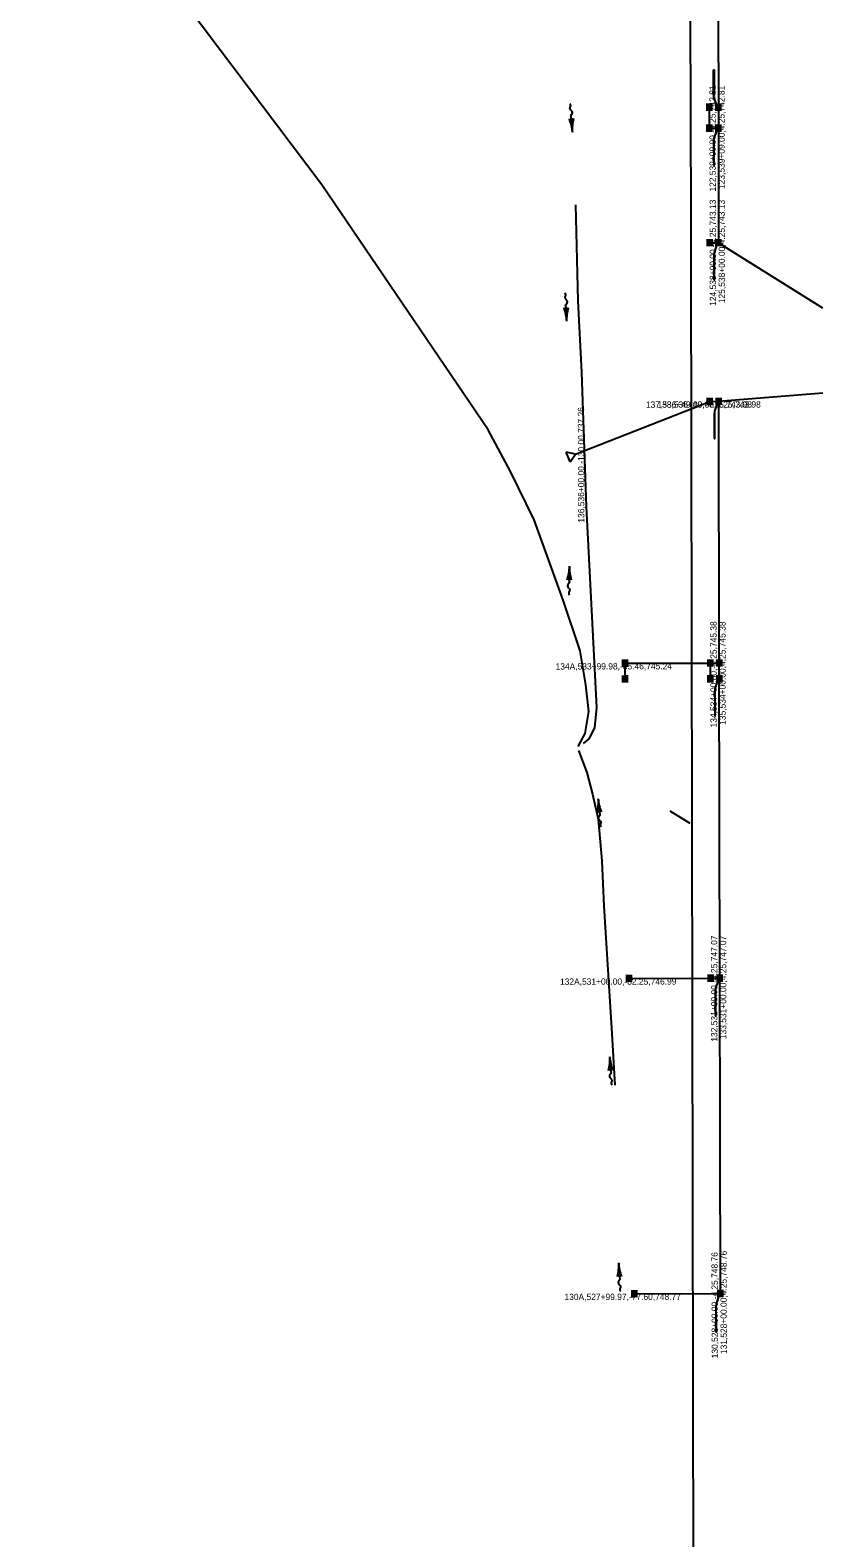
# Model space of a CAD drawing. Extents: x 593481 to 595859, y 101157 to 225994.
# Drawn here: x 593709 to 594464, y 151843 to 153277 of the extents above; entities that cross this region are included whole.
import ezdxf

# ---------------------------------------------------------------- set-up
doc = ezdxf.new("R2010")
doc.units = 0
for name, color, linetype in [('Default', 7, 'Continuous'), ('E_DTM_SpotElev', 7, 'Continuous'), ('E_PROF_GridMin', 7, 'Continuous'), ('Level 6', 7, 'Continuous'), ('P_DRN_SS_UG', 7, 'Continuous'), ('P_RDWY_C_and_G_H', 7, 'Continuous')]:
    doc.layers.add(name, color=color, linetype=linetype)

msp = doc.modelspace()

# ---------------------------------------------------------------- linework, layer by layer
at = {"layer": 'Default'}
msp.add_line((594345.1, 149542.4), (594338.5, 153236.3), dxfattribs=at)
msp.add_arc((250574.3, 152618.3), 343764.7, 0.103013, 0.29409, dxfattribs=at)
at = {"layer": 'E_DTM_SpotElev'}
for p, q in [((594225.9, 153180.4), (594224.8, 153194.5)), ((594220.4, 153000.5), (594219.8, 153014.6)), ((594222.9, 152767.2), (594222.7, 152753.1)), ((594250.4, 152546.1), (594251.6, 152532)), ((594261.4, 152300.5), (594262.3, 152286.4)), ((594269.9, 152104.3), (594270.6, 152090.2))]:
    msp.add_line(p, q, dxfattribs=at)
for points in [[(594222.9, 153193), (594225.1, 153190), (594226.9, 153193.3)], [(594217.8, 153013.2), (594219.9, 153010), (594221.8, 153013.3)], [(594224.8, 152754.4), (594222.8, 152757.6), (594220.8, 152754.4)], [(594253.5, 152533.5), (594251.2, 152536.5), (594249.5, 152533.1)], [(594264.2, 152287.8), (594262, 152290.9), (594260.2, 152287.6)], [(594272.5, 152091.6), (594270.4, 152094.7), (594268.5, 152091.4)]]:
    msp.add_lwpolyline(points, dxfattribs=at)
for centre, start, end in [((594184.1, 153177), 4.6994, 22.4617), ((594267.7, 153183.8), 166.9371, 184.6994), ((594178.4, 152998.7), 2.4314, 20.1937), ((594262.3, 153002.2), 164.6691, 182.4314), ((594181, 152767.8), 341.4611, 359.2234), ((594264.9, 152766.6), 179.2234, 196.9857), ((594208.6, 152542.3), 347.3129, 5.0752), ((594292.2, 152549.8), 185.0752, 202.8376), ((594219.5, 152297.9), 345.7579, 3.5203), ((594303.3, 152303), 183.5203, 201.2826), ((594228, 152102.1), 345.2441, 3.0064), ((594311.8, 152106.5), 183.0064, 200.7687)]:
    msp.add_arc(centre, 42, start, end, dxfattribs=at)
for points in [[(594224.8, 153194.5), (594224.4, 153195.2), (594226, 153199), (594223.5, 153202.7), (594224.2, 153205.6), (594223.4, 153207.3)], [(594219.8, 153014.6), (594219.4, 153015.3), (594221.1, 153019), (594218.8, 153022.9), (594219.6, 153025.7), (594218.9, 153027.4)], [(594222.7, 152753.1), (594223, 152752.3), (594221.1, 152748.7), (594223.3, 152744.8), (594222.3, 152741.9), (594222.9, 152740.2)], [(594251.6, 152532), (594252, 152531.2), (594250.5, 152527.5), (594253, 152523.8), (594252.3, 152520.9), (594253.1, 152519.2)], [(594262.3, 152286.4), (594262.6, 152285.6), (594261, 152281.9), (594263.4, 152278.1), (594262.7, 152275.2), (594263.4, 152273.5)], [(594270.6, 152090.2), (594271, 152089.4), (594269.3, 152085.7), (594271.7, 152081.9), (594270.9, 152079.1), (594271.6, 152077.4)]]:
    msp.add_spline(points, degree=3, dxfattribs=at)
at = {"layer": 'E_PROF_GridMin'}
for p, q in [((594364.3, 153455.3), (594364.8, 153184.2)), ((594356.3, 153184.2), (594356.3, 153204.2)), ((594356.3, 153184.2), (594364.8, 153184.2)), ((594364.8, 153184.2), (594365, 153075.2)), ((594356.5, 153075.2), (594365, 153075.2)), ((594365, 153075.2), (594463.9, 153013.1)), ((594228.7, 152874.1), (594356.8, 152924.2)), ((594356.8, 152924.2), (594365.3, 152924.3)), ((594365.3, 152924.3), (594464.3, 152932.3)), ((594365.7, 152675.3), (594365.3, 152924.3)), ((594276, 152675.1), (594357.2, 152675.2)), ((594276, 152660.1), (594276, 152675.1)), ((594357.2, 152675.2), (594365.7, 152675.3)), ((594357.3, 152660.2), (594357.2, 152675.2)), ((594366.3, 152375.3), (594365.7, 152675.3)), ((594337.9, 152522.4), (594318.8, 152534.1)), ((594279.8, 152375.1), (594357.8, 152375.2)), ((594357.8, 152375.2), (594366.3, 152375.3)), ((594366.8, 152075.3), (594366.3, 152375.3)), ((594285, 152075.1), (594358.3, 152075.2)), ((594358.3, 152075.2), (594366.8, 152075.3))]:
    msp.add_line(p, q, dxfattribs=at)
for points in [[(594231.3, 152595.8), (594238, 152608), (594241.5, 152629.1), (594238.7, 152654.6), (594233.1, 152686.7), (594216.9, 152735.1), (594189.3, 152811.5), (594166.9, 152857.5), (594145.5, 152897.2), (593987.3, 153130.1), (593816.8, 153356.3), (593736.8, 153457), (593709.5, 153500.1)], [(594363.5, 153205.3), (594360.5, 153213.8), (594360.5, 153215.8)], [(594363.5, 153183.3), (594360.6, 153174.8), (594360.6, 153172.8)], [(594236.5, 152598.7), (594241.9, 152603), (594247.3, 152613.7), (594249, 152632.8), (594239.2, 152824), (594234.7, 152952), (594231.2, 153020), (594229, 153111.2)], [(594363.7, 153074.3), (594360.8, 153065.8), (594360.8, 153063.8)], [(594363.9, 152923.3), (594361, 152914.8), (594361.1, 152912.8)], [(594364.4, 152659.2), (594361.5, 152650.7), (594361.5, 152648.7)], [(594231.7, 152592), (594239.5, 152571.2), (594244.9, 152550.4), (594250.2, 152526.5), (594253.7, 152487.1), (594255.7, 152444), (594262.9, 152327.7), (594266.1, 152273.5)], [(594364.9, 152374.2), (594362, 152365.7), (594362, 152363.7)], [(594365.5, 152074.2), (594362.6, 152065.6), (594362.6, 152063.6)]]:
    msp.add_lwpolyline(points, dxfattribs=at)
at = {"layer": 'P_DRN_SS_UG'}
for p, q in [((594354, 153200.8), (594354, 153207.7)), ((594354.9, 153200.8), (594354.9, 153207.7)), ((594355.8, 153200.8), (594355.8, 153207.7)), ((594356.7, 153200.8), (594356.7, 153207.7)), ((594357.6, 153200.8), (594357.6, 153207.7)), ((594358.5, 153200.8), (594358.5, 153207.7)), ((594362.6, 153200.8), (594362.6, 153207.7)), ((594363.5, 153200.8), (594363.5, 153207.7)), ((594364.4, 153200.8), (594364.4, 153207.7)), ((594365.3, 153200.8), (594365.3, 153207.7)), ((594366.2, 153200.8), (594366.2, 153207.7)), ((594367.1, 153200.8), (594367.1, 153207.7)), ((594354.1, 153180.8), (594354.1, 153187.7)), ((594355, 153180.8), (594355, 153187.7)), ((594355.9, 153180.8), (594355.9, 153187.7)), ((594356.8, 153180.8), (594356.8, 153187.7)), ((594357.7, 153180.8), (594357.7, 153187.7)), ((594358.6, 153180.8), (594358.6, 153187.7)), ((594362.6, 153180.8), (594362.6, 153187.7)), ((594363.5, 153180.8), (594363.5, 153187.7)), ((594364.4, 153180.8), (594364.4, 153187.7)), ((594365.3, 153180.8), (594365.3, 153187.7)), ((594366.2, 153180.8), (594366.2, 153187.7)), ((594367.1, 153180.8), (594367.1, 153187.7)), ((594354.3, 153071.8), (594354.3, 153078.7)), ((594355.2, 153071.8), (594355.2, 153078.7)), ((594356.1, 153071.8), (594356.1, 153078.7)), ((594357, 153071.8), (594357, 153078.7)), ((594357.9, 153071.8), (594357.9, 153078.7)), ((594358.8, 153071.8), (594358.8, 153078.7)), ((594362.8, 153071.8), (594362.8, 153078.7)), ((594363.7, 153071.8), (594363.7, 153078.7)), ((594364.6, 153071.8), (594364.6, 153078.7)), ((594365.5, 153071.8), (594365.5, 153078.7)), ((594366.4, 153071.8), (594366.4, 153078.7)), ((594367.3, 153071.8), (594367.3, 153078.7)), ((594354.5, 152920.8), (594354.5, 152927.7)), ((594355.4, 152920.8), (594355.4, 152927.7)), ((594356.3, 152920.8), (594356.3, 152927.7)), ((594357.2, 152920.8), (594357.2, 152927.7)), ((594358.1, 152920.8), (594358.1, 152927.7)), ((594359, 152920.8), (594359, 152927.7)), ((594363, 152920.8), (594363, 152927.7)), ((594363.9, 152920.8), (594363.9, 152927.7)), ((594364.8, 152920.8), (594364.8, 152927.7)), ((594365.7, 152920.8), (594365.7, 152927.7)), ((594366.6, 152920.8), (594366.6, 152927.7)), ((594367.5, 152920.8), (594367.5, 152927.7)), ((594273.8, 152671.6), (594273.7, 152678.5)), ((594274.7, 152671.6), (594274.6, 152678.5)), ((594275.6, 152671.6), (594275.5, 152678.5)), ((594276.5, 152671.6), (594276.4, 152678.5)), ((594277.4, 152671.7), (594277.3, 152678.5)), ((594278.3, 152671.7), (594278.2, 152678.6)), ((594355, 152671.8), (594355, 152678.7)), ((594355.9, 152671.8), (594355.9, 152678.7)), ((594356.8, 152671.8), (594356.8, 152678.7)), ((594357.7, 152671.8), (594357.7, 152678.7)), ((594358.6, 152671.8), (594358.6, 152678.7)), ((594359.5, 152671.8), (594359.5, 152678.7)), ((594363.5, 152671.8), (594363.5, 152678.7)), ((594364.4, 152671.8), (594364.4, 152678.7)), ((594365.3, 152671.8), (594365.3, 152678.7)), ((594366.2, 152671.8), (594366.2, 152678.7)), ((594367.1, 152671.8), (594367.1, 152678.7)), ((594368, 152671.8), (594368, 152678.7)), ((594273.9, 152656.6), (594273.7, 152663.5)), ((594274.8, 152656.6), (594274.6, 152663.5)), ((594275.7, 152656.6), (594275.5, 152663.5)), ((594276.6, 152656.7), (594276.4, 152663.5)), ((594277.5, 152656.7), (594277.3, 152663.6)), ((594278.4, 152656.7), (594278.2, 152663.6)), ((594355, 152656.8), (594355, 152663.7)), ((594355.9, 152656.8), (594355.9, 152663.7)), ((594356.8, 152656.8), (594356.8, 152663.7)), ((594357.7, 152656.8), (594357.7, 152663.7)), ((594358.6, 152656.8), (594358.6, 152663.7)), ((594359.5, 152656.8), (594359.5, 152663.7)), ((594363.5, 152656.8), (594363.5, 152663.7)), ((594364.4, 152656.8), (594364.4, 152663.7)), ((594365.3, 152656.8), (594365.3, 152663.7)), ((594366.2, 152656.8), (594366.2, 152663.7)), ((594367.1, 152656.8), (594367.1, 152663.7)), ((594368, 152656.8), (594368, 152663.7)), ((594277.5, 152371.7), (594277.5, 152378.5)), ((594278.4, 152371.7), (594278.4, 152378.5)), ((594279.3, 152371.7), (594279.3, 152378.5)), ((594280.2, 152371.7), (594280.2, 152378.5)), ((594281.1, 152371.7), (594281.1, 152378.5)), ((594282, 152371.7), (594282, 152378.5)), ((594355.5, 152371.8), (594355.5, 152378.7)), ((594356.4, 152371.8), (594356.4, 152378.7)), ((594357.3, 152371.8), (594357.3, 152378.7)), ((594358.2, 152371.8), (594358.2, 152378.7)), ((594359.1, 152371.8), (594359.1, 152378.7)), ((594360, 152371.8), (594360, 152378.7)), ((594364, 152371.8), (594364, 152378.7)), ((594364.9, 152371.8), (594364.9, 152378.7)), ((594365.8, 152371.8), (594365.8, 152378.7)), ((594366.7, 152371.8), (594366.7, 152378.7)), ((594367.6, 152371.8), (594367.6, 152378.7)), ((594368.5, 152371.8), (594368.5, 152378.7)), ((594282.8, 152071.6), (594282.6, 152078.4)), ((594283.7, 152071.6), (594283.5, 152078.5)), ((594284.6, 152071.6), (594284.4, 152078.5)), ((594285.5, 152071.7), (594285.3, 152078.5)), ((594286.4, 152071.7), (594286.2, 152078.6)), ((594287.3, 152071.7), (594287.1, 152078.6)), ((594364.6, 152071.8), (594364.6, 152078.7)), ((594365.5, 152071.8), (594365.5, 152078.7)), ((594366.4, 152071.8), (594366.4, 152078.7)), ((594367.3, 152071.8), (594367.3, 152078.7)), ((594368.2, 152071.8), (594368.2, 152078.7)), ((594369.1, 152071.8), (594369.1, 152078.7))]:
    msp.add_line(p, q, dxfattribs=at)
for points in [[(594360.2, 153239.8), (594360.7, 153239.8), (594360.7, 153215.8), (594360.3, 153215.8)], [(594357.3, 153203.2), (594357.3, 153205.2), (594355.3, 153205.2), (594355.3, 153203.2)], [(594365.8, 153203.3), (594365.8, 153205.3), (594363.8, 153205.3), (594363.8, 153203.3)], [(594357.3, 153183.2), (594357.3, 153185.2), (594355.3, 153185.2), (594355.3, 153183.2)], [(594365.8, 153183.3), (594365.8, 153185.3), (594363.8, 153185.2), (594363.8, 153183.2)], [(594360.4, 153148.8), (594360.9, 153148.8), (594360.8, 153172.8), (594360.3, 153172.8)], [(594357.5, 153074.2), (594357.5, 153076.2), (594355.5, 153076.2), (594355.5, 153074.2)], [(594366, 153074.3), (594366, 153076.3), (594364, 153076.2), (594364, 153074.2)], [(594360.6, 153039.8), (594361.1, 153039.8), (594361, 153063.8), (594360.5, 153063.8)], [(594357.8, 152923.2), (594357.8, 152925.2), (594355.8, 152925.2), (594355.8, 152923.2)], [(594366.3, 152923.3), (594366.3, 152925.3), (594364.3, 152925.2), (594364.3, 152923.2)], [(594360.9, 152888.8), (594361.3, 152888.8), (594361.3, 152912.8), (594360.8, 152912.8)], [(594277, 152674.1), (594277, 152676.1), (594275, 152676), (594275, 152674)], [(594358.2, 152674.2), (594358.2, 152676.2), (594356.2, 152676.2), (594356.2, 152674.2)], [(594366.7, 152674.3), (594366.7, 152676.3), (594364.7, 152676.2), (594364.7, 152674.2)], [(594277.1, 152659.1), (594277, 152661.1), (594275, 152661.1), (594275.1, 152659.1)], [(594358.3, 152659.2), (594358.3, 152661.2), (594356.3, 152661.2), (594356.3, 152659.2)], [(594366.8, 152659.3), (594366.8, 152661.3), (594364.8, 152661.3), (594364.8, 152659.3)], [(594361.3, 152624.7), (594361.8, 152624.7), (594361.8, 152648.7), (594361.3, 152648.7)], [(594358.8, 152374.2), (594358.8, 152376.2), (594356.8, 152376.2), (594356.8, 152374.2)], [(594367.3, 152374.3), (594367.3, 152376.3), (594365.3, 152376.2), (594365.3, 152374.2)], [(594280.8, 152374.1), (594280.8, 152376.1), (594278.8, 152376.1), (594278.8, 152374.1)], [(594361.8, 152339.7), (594362.3, 152339.7), (594362.3, 152363.7), (594361.8, 152363.7)], [(594286, 152074.1), (594285.9, 152076.1), (594283.9, 152076), (594284, 152074)], [(594367.8, 152074.3), (594367.8, 152076.3), (594365.8, 152076.2), (594365.8, 152074.2)], [(594362.4, 152038.6), (594362.9, 152038.6), (594362.8, 152063.6), (594362.3, 152063.6)]]:
    msp.add_lwpolyline(points, close=True, dxfattribs=at)
at = {"layer": 'P_RDWY_C_and_G_H'}
for p, q in [((594228.7, 152874.1), (594219.9, 152876)), ((594223.6, 152866.7), (594219.9, 152876)), ((594223.6, 152866.7), (594228.7, 152874.1))]:
    msp.add_line(p, q, dxfattribs=at)

# ---------------------------------------------------------------- texts
at = {"layer": 'Level 6'}
for s, rotation, p in [('122,539+09.00,-4.25,742.81', 90.103, (594362.4, 153123.8)), ('123,539+09.00,4.25,742.81', 90.103, (594370.9, 153126.2)), ('124,538+00.00,-4.25,743.13', 90.103, (594362.6, 153015.1)), ('125,538+00.00,4.25,743.13', 90.103, (594371.1, 153017.6)), ('137,536+49.00,-4.25,743.98', 0.103, (594295.8, 152918.1)), ('138,536+49.00,4.25,743.98', 0.103, (594306.8, 152918.1)), ('136,536+00.00,-130.00,737.26', 90.103, (594237.2, 152808.8)), ('134,534+00.00,-4.25,745.38', 90.103, (594363.3, 152613.9)), ('135,534+00.00,4.25,745.38', 90.103, (594371.8, 152616.4)), ('134A,533+99.98,-85.46,745.24', 0.103, (594209.8, 152669)), ('132,531+00.00,-4.25,747.07', 90.103, (594363.9, 152314.9)), ('133,531+00.00,4.25,747.07', 90.103, (594372.4, 152317.3)), ('132A,531+00.00,-82.25,746.99', 0.103, (594214, 152369)), ('130,528+00.00,-4.25,748.76', 90.103, (594364.4, 152013.6)), ('131,528+00.00,4.25,748.76', 90.103, (594372.9, 152017.6)), ('130A,527+99.97,-77.60,748.77', 0.103, (594218.3, 152069))]:
    msp.add_text(s, height=6, rotation=rotation, dxfattribs=at).set_placement(p)

doc.saveas('drawing.dxf')
